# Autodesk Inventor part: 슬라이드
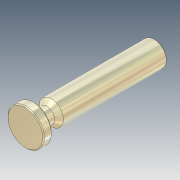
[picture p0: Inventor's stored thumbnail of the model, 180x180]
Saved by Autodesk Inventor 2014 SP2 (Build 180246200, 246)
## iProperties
Company: 한국ATC센터
Created: 2014-10
Part Number: 슬라이드
Document SubType Name: Modeling
Designer: 한국ATC센터
Density: 7.86 g/cm^3
Material: 강철, 연강
Mass: 702.202 g
Surface Area: 150.69 cm^2
Volume: 89.3387 cm^3
Appearance: 티타늄 - 광택
Author: KYOUNG IL JANG
Revision Number: 1
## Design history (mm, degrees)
sketch "스케치1"
  geometry: L1 (-14, 195)-(-14, 171) reference; L2 (19, 106.5)-(-19, 106.5) reference; L3 (0, 106.5)-(0, 256.5); L4 (0, 256.5)-(-14, 256.5); L5 (-14, 256.5)-(-14, 136.5); L6 (-14, 116.5)-(-21, 116.5); L7 (-21, 116.5)-(-21, 106.5); L8 (-21, 106.5)-(0, 106.5); L9 (-14, 116.5)-(-9, 116.5); L10 (-9, 116.5)-(-9, 131.5); L11 (-9, 131.5)-(-14, 136.5); L12 (-14, 136.5)-(-14, 116.5); 1 further point
  constraints: 24 end point, 5 perpendicular, 3 parallel, 1 collinear, 1 horizontal, 1 midpoint, 1 point on line, 1 vertical, 4 other
  dimensions: "d0" = 10 distance between parallel lines of L6 L8; "d1" = 42 diameter of L7 L3; "d2" = 150 distance of L3.start L3.end; "d3" = 135 deg angle of L11 L5; "d4" = 18 diameter of L10 L3; "d5" = 30 distance from line of L5.end L8
revolve "회전1" sketch "스케치1" stored, may be unused: angle "d6" = 90 deg
chamfer "모따기1" distance "d7" = 1; stored, may be unused: second distance "d8" = 2, angle "d9" = 45 deg
fillet "모깎기1" dims "d10" = 2
node "솔리드1"
